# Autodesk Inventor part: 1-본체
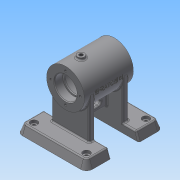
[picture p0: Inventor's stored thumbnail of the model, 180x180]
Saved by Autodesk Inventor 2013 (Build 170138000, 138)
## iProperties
Created: 2016-07
Part Number: 1-본체
Material: 일반
Document SubType Name: Modeling
Designer: Administrator
Density: 1 g/cm^3
Author: Administrator
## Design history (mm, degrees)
sketch "스케치1"
  geometry: L1 (-50, 55)-(50, 55); L2 (50, 55)-(50, 20); L3 (50, 20)-(-50, 20); L4 (-50, 20)-(-50, 55); 1 further point
  constraints: 8 end point, 2 parallel, 1 horizontal, 1 perpendicular
  dimensions: "d0" = 100 distance of L1.start L1.end; "d2" = 35 distance of L3.end L1.start; "d3" = 55 distance from line of point (0, 0) L1; "d4" = 50 distance from line of point (0, 0) L4
extrude "돌출1" new body sketch "스케치1" distance "d5" = 12; taper "d6" = 0 deg
node "작업 평면1"
sketch "스케치2"
  geometry: L1 (-35, 70)-(35, 70); L2 (-35, 70)-(35, 70); L3 (35, 70)-(35, 97); L4 (35, 97)-(-35, 97); L5 (-35, 97)-(-35, 70); 1 further point
  constraints: 10 end point, 2 horizontal, 2 parallel, 1 perpendicular
  dimensions: "d8" = 70 distance from line of point (0, 0) L1; "d9" = 70 distance of L1.start L1.end; "d10" = 35 horizontal distance of point (0, 0) L1.start; "d11" = 54 diameter of L4 L1
revolve "회전1" sketch "스케치2" stored, may be unused: angle "d12" = 90 deg
sketch "스케치3"
  geometry: L1 (0, -12)-(100, -12) reference; L2 (77, -70)-(23, -70); L3 (23, -70)-(23, -12); L4 (23, -12)-(77, -12); L5 (77, -12)-(77, -70); 2 further points
  constraints: 8 end point, 2 midpoint, 2 parallel, 1 horizontal, 1 perpendicular
  dimensions: "d13" = 54 distance between parallel lines of L3 L5; "d15" = 27 distance from line of point (50, 0) L5; "d16" = 58 distance of L2.end L3.end
extrude "돌출2" join sketch "스케치3" distance "d17" = 8; taper "d18" = 0 deg
sketch "스케치4"
  geometry: L1 (-22.876, 44.652)-(22.814, 44.652) reference; L2 (22.814, 44.652)-(22.814, 22) reference; L3 (22.814, 22)-(-22.876, 22); L4 (-22.876, 22)-(-22.876, 44.652) reference; L5 (-35, 43)-(35, 43) reference; 1 further point
  constraints: 8 end point, 2 horizontal, 2 parallel, 2 vertical, 1 perpendicular
  dimensions: "d21" = 21 distance between parallel lines of L3 L5
extrude "돌출3" join sketch "스케치4" stored distance "d22" = 8; taper "d23" = 0 deg
sketch "스케치5"
  geometry: L1 (-22, -20)-(-22, 20) reference; L2 (-35.5, -8)-(-35.5, 8); L3 (-28.5, -8)-(-28.5, 8); L4 (0, 55)-(0, 20) reference; L5 (-35.5, 0)-(-28.5, 0); L6 (-43, -35)-(-97, -35) reference; A1 r 3.5 centre (-32, -8) between (-35.5, -8) and (-28.5, -8); A2 r 3.5 centre (-32, 8) between (-28.5, 8) and (-35.5, 8); 1 further point
  constraints: 6 end point, 4 point on circle, 4 tangent, 2 centre point, 2 midpoint, 1 parallel, 1 vertical
  dimensions: "d24" = 3.5 radius of A2; "d26" = 32 distance from line of L4 A2.centre; "d27" = 16 distance of A2.centre A1.centre; "d28" = 35 distance between parallel lines of L5 L6
extrude "돌출4" cut sketch "스케치5" stored distance "d29" = 0; taper "d30" = 0 deg
node "작업 평면2"
sketch "스케치6"
  geometry: L1 (27, -35)-(-27, -35) reference; C1 r 5 at (0, -13); 1 further point
  constraints: 1 centre point, 1 vertical alignment
  dimensions: "d32" = 10 diameter of C1; "d34" = 22 distance from line of C1.centre L1
extrude "돌출5" join sketch "스케치6" stored distance "d35" = 8; taper "d36" = 0 deg
sketch "스케치10"
  geometry: L1 (-35, 70)-(35, 70); L2 (-35, 43)-(-35, 97) reference; L3 (20, 0)-(55, 0) reference; L4 (-35, 70)-(-23, 70); L5 (-23, 70)-(-23, 86); L6 (-23, 86)-(-35, 86); L7 (-35, 86)-(-35, 70); L8 (-23, 70)-(-21, 70); L9 (-21, 70)-(-21, 84); L10 (-21, 84)-(-23, 84); L11 (-23, 84)-(-23, 70); L12 (-21, 70)-(21, 70); L13 (21, 70)-(21, 92); L14 (21, 92)-(-21, 92); L15 (-21, 92)-(-21, 70); L16 (21, 70)-(23, 70); L17 (23, 70)-(23, 84); L18 (23, 84)-(21, 84); L19 (21, 84)-(21, 70); L20 (23, 70)-(35, 70); L21 (35, 70)-(35, 86); L22 (35, 86)-(23, 86); L23 (23, 86)-(23, 70); 1 further point
  constraints: 42 end point, 10 parallel, 6 horizontal, 5 perpendicular, 1 midpoint
  dimensions: "d48" = 70 distance of L1.end L1.start; "d50" = 70 distance between parallel lines of L3 L1; "d51" = 32 diameter of L6 L1; "d52" = 12 distance between parallel lines of L5 L2; "d53" = 28 diameter of L10 L1; "d54" = 2 distance between parallel lines of L15 L5; "d55" = 44 diameter of L14 L1; "d56" = 42 distance between parallel lines of L19 L15; "d57" = 28 diameter of L18 L1; "d58" = 2 distance between parallel lines of L17 L19; "d60" = 32 diameter of L22 L1
revolve "회전2" sketch "스케치10" stored, may be unused: angle "d61" = 90 deg
chamfer "모따기2" distance "d62" = 1; stored, may be unused: second distance "d63" = 2, angle "d64" = 45 deg
fillet "모깎기1" dims "d65" = 0.3
node "작업 평면3"
sketch "스케치11"
  geometry: L1 (0, 70)-(15.898, 44.559); L2 (0, 70)-(0, 58.695); C1 r 27 at (0, 70) reference; 1 further point
  constraints: 4 end point, 1 vertical
  dimensions: "d69" = 32 deg angle of L2 L1; "d70" = 30 distance of L1.start L1.end
node "작업 평면4"
sketch "스케치12"
  geometry: C1 r 6 at (0, 0); 2 further points
  constraints: 1 centre point, 1 coincident
  dimensions: "d71" = 12 diameter of C1
extrude "돌출7" join sketch "스케치12" stored distance "d73" = 42; taper "d74" = 0 deg
sketch "스케치13"
  geometry: C1 r 27 at (0, 0) reference; 2 further points
  constraints: 1 vertical alignment
  dimensions: "d75" = 21 distance of C1.centre point (0, -21)
hole "구멍1" sketch "스케치13" at (0, -21) diameter "d76" = 3.242; stored, may be unused: countersink angle "d80" = 90 deg, drill point angle "d82" = 120 deg; dims "d77" = 8, "d78" = 4, "d79" = 2, "d81" = 10
hole "구멍2" diameter "d88" = 5.188; stored, may be unused: countersink angle "d92" = 90 deg, drill point angle "d94" = 120 deg; dims "d86" = 10, "d87" = 10, "d89" = 8, "d90" = 4, "d91" = 2, "d93" = 10
hole "구멍3" diameter "d97" = 5.188; stored, may be unused: countersink angle "d101" = 90 deg, drill point angle "d103" = 120 deg; dims "d95" = 10, "d96" = 10, "d98" = 8, "d99" = 4, "d100" = 2, "d102" = 10
node "작업 평면5"
sketch "스케치14"
  geometry: L1 (-35, 43)-(-35, 97) reference; L2 (-35, 97)-(35, 97) reference; 2 further points
  constraints: 1 other
  dimensions: "d105" = 35 distance from line of point (0, 70) L1; "d106" = 27 distance from line of point (0, 70) L2
feature "엠보싱1" sketch "스케치14" dims "d107" = 0.5, "d108" = 0
sketch "스케치15"
  geometry: L1 (-23, 8)-(-23, -27) reference; L2 (-23, -27)-(77, -27) reference; 5 further points
  dimensions: "d119" = 12.5 distance from line of L1 point (-10.5, -14.5); "d120" = 12.5 distance from line of L2 point (-10.5, -14.5)
hole "구멍4" sketch "스케치15" at (-10.5, -14.5) diameter "d121" = 6; stored, may be unused: countersink angle "d125" = 90 deg, drill point angle "d127" = 120 deg; dims "d122" = 8, "d123" = 10, "d124" = 4, "d126" = 10
feature "면 기울기3" dims angle "d128" = 20 deg
feature "면 기울기4" dims angle "d129" = 20 deg
fillet "모깎기6" dims "d130" = 10, "d131" = 5
fillet "모깎기7" dims "d132" = 10, "d133" = 5
fillet "모깎기8" dims "d134" = 10, "d135" = 5
fillet "모깎기9" dims "d136" = 10, "d137" = 5
fillet "모깎기10" dims "d138" = 2
fillet "모깎기11" dims "d139" = 2
fillet "모깎기12" dims "d140" = 2
fillet "모깎기15" dims "d143" = 2
fillet "모깎기16" dims "d144" = 2
fillet "모깎기17" dims "d145" = 2
fillet "모깎기18" dims "d146" = 2
fillet "모깎기21" dims "d149" = 2
fillet "모깎기24" dims "d152" = 2
fillet "모깎기25" dims "d153" = 2
fillet "모깎기26" dims "d154" = 2
node "솔리드1"
mirror "대칭1"
mirror "대칭2"
pattern_circular "원형 패턴1" dims angle "d84" = 360 deg
mirror "대칭3"
mirror "대칭4"
mirror "대칭5"
other parameters: "d7" = 0, "d68" = 0
